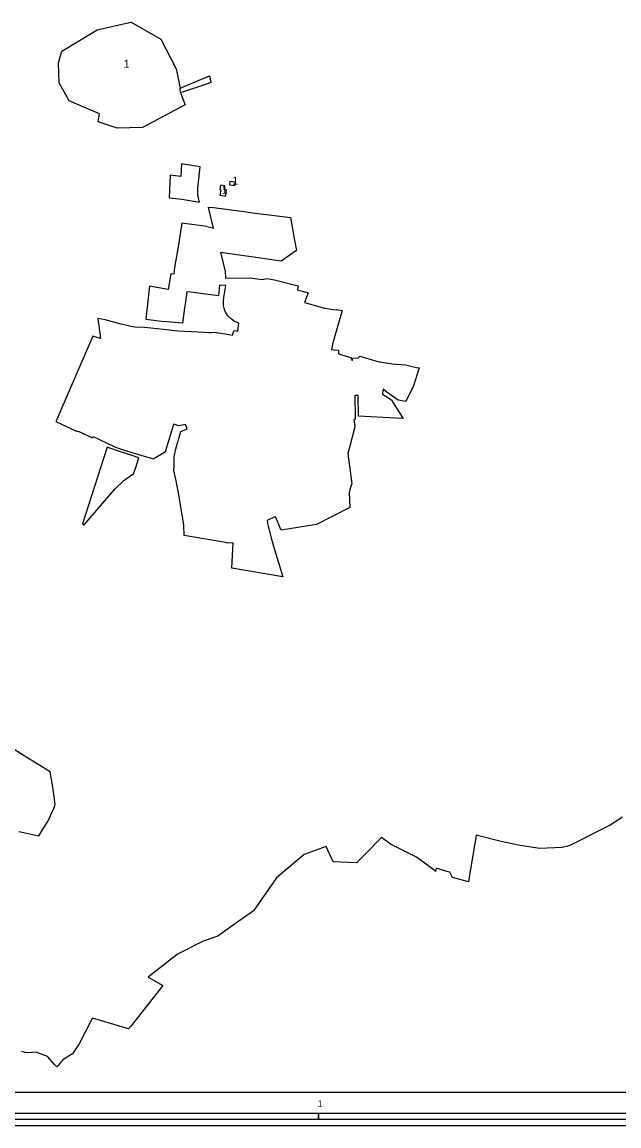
# Model space of a CAD drawing. Extents: x -790696 to -787271, y -1142331 to -1139378.
# Drawn here: x -789536 to -788602, y -1142329 to -1140605 of the extents above; entities that cross this region are included whole.
import ezdxf

# ---------------------------------------------------------------- set-up
doc = ezdxf.new("R2010")
doc.units = 0
for name, color, linetype in [('GR_MER', 7, 'Continuous'), ('NERES_HRA', 7, 'Continuous'), ('NERES_SET', 7, 'Continuous'), ('OVNE_PRE', 7, 'Continuous'), ('OVNE_SET', 7, 'Continuous'), ('OVNI_SET', 7, 'Continuous'), ('OZN', 7, 'Continuous')]:
    doc.layers.add(name, color=color, linetype=linetype)

msp = doc.modelspace()

# ---------------------------------------------------------------- linework, layer by layer
at = {"layer": 'GR_MER'}
for points in [[(-788475.3, -1142276.8), (-788475.3, -1142329.3), (-790086.7, -1142329.3), (-790086.7, -1142276.8), (-788475.3, -1142276.8)], [(-788572.2, -1142319.3), (-789072.2, -1142319.3), (-789072.2, -1142309.3), (-788572.2, -1142309.3)]]:
    msp.add_lwpolyline(points, dxfattribs=at)
msp.add_lwpolyline([(-789072.2, -1142319.3), (-789572.2, -1142319.3), (-789572.2, -1142309.3), (-789072.2, -1142309.3)], close=True, dxfattribs=at)
at = {"layer": 'NERES_HRA'}
msp.add_line((-789287.7, -1140715.3), (-789288.2, -1140708.2), dxfattribs=at)
at = {"layer": 'NERES_SET'}
for p, q in [((-789365.2, -1140604.8), (-789365.2, -1140604.8)), ((-789396.1, -1140751.4), (-789396.1, -1140751.4)), ((-789396.1, -1140751.4), (-789396.1, -1140751.4))]:
    msp.add_line(p, q, dxfattribs=at)
for points in [[(-789365.2, -1140604.8), (-789318.6, -1140631.6), (-789294.4, -1140677.6), (-789288.2, -1140708.2), (-789242.4, -1140688.7), (-789240.6, -1140699.2), (-789248.8, -1140702.2), (-789287.7, -1140715.3), (-789280.6, -1140733.8), (-789347.5, -1140769.6), (-789386.7, -1140770.7), (-789416.6, -1140760.4), (-789414.6, -1140748.3), (-789446.4, -1140734.5), (-789461.9, -1140727.7), (-789477.8, -1140699.9), (-789478.5, -1140668.2), (-789473.5, -1140650.4), (-789418.2, -1140617), (-789367.8, -1140605.3), (-789365.2, -1140604.8)], [(-789225.5, -1140859.3), (-789226.5, -1140866.4), (-789225, -1140866.6), (-789226.4, -1140875.3), (-789217.3, -1140876.7), (-789215.9, -1140867.6), (-789219.5, -1140867.1), (-789218.5, -1140860.4), (-789225.5, -1140859.3)], [(-789210.5, -1140853.9), (-789211.2, -1140858.8), (-789203.2, -1140860), (-789202.5, -1140855), (-789210.5, -1140853.9)]]:
    msp.add_lwpolyline(points, dxfattribs=at)
at = {"layer": 'OVNE_PRE'}
msp.add_lwpolyline([(-788596.7, -1141846.8), (-788616.1, -1141859.5), (-788679.2, -1141891.4), (-788682.3, -1141892.2), (-788691.5, -1141894.3), (-788726.1, -1141895.7), (-788757.1, -1141891), (-788779.4, -1141886.3), (-788786.7, -1141884.8), (-788825.8, -1141874.8), (-788837.3, -1141944.5), (-788837.9, -1141948), (-788843.4, -1141946.5), (-788862.6, -1141941.4), (-788866.8, -1141933.1), (-788869.6, -1141932.2), (-788888, -1141926.5), (-788889.1, -1141931.7), (-788891.4, -1141929.9), (-788919.1, -1141909.4), (-788959.6, -1141888.9), (-788973.9, -1141878.8), (-788999.4, -1141904.9), (-789006.3, -1141912.1), (-789012, -1141918.2), (-789049.2, -1141916.6), (-789060.1, -1141892.9), (-789094.4, -1141905.5), (-789137.7, -1141941.8), (-789173.8, -1141993.5), (-789205.5, -1142015.7), (-789229.6, -1142032.6), (-789249.1, -1142039.6), (-789253.6, -1142041.3), (-789292.4, -1142060.8), (-789338.2, -1142096.8), (-789315.7, -1142109.8)], dxfattribs=at)
at = {"layer": 'OVNE_SET'}
for points in [[(-789540.5, -1141869.1), (-789509.3, -1141875.9), (-789494.8, -1141852.6), (-789488.3, -1141838.5), (-789486, -1141833.3), (-789484.5, -1141828.7), (-789483.9, -1141826.5), (-789487.3, -1141799.8), (-789491.8, -1141776.2), (-789532.5, -1141750.9), (-789574.4, -1141724.8)], [(-789315.7, -1142109.8), (-789365, -1142172.7), (-789369, -1142177.7), (-789425.6, -1142161.1), (-789427.3, -1142164.6), (-789436.7, -1142182.8), (-789446.1, -1142200.9), (-789456.5, -1142216.7), (-789471.6, -1142226.1), (-789479.4, -1142235.3), (-789481.4, -1142236.9), (-789484.1, -1142233.9), (-789495.7, -1142220.8), (-789513.3, -1142214.1), (-789526.8, -1142215.2)], [(-789526.8, -1142215.2), (-789530.6, -1142214.6), (-789536, -1142212.8)]]:
    msp.add_lwpolyline(points, dxfattribs=at)
at = {"layer": 'OVNI_SET'}
msp.add_line((-789246.7, -1140924.3), (-789236.4, -1140926.6), dxfattribs=at)
for points in [[(-789257.1, -1140831), (-789286.3, -1140826.4), (-789287.1, -1140846.1), (-789304, -1140843.8), (-789305.5, -1140879.5), (-789285.1, -1140881.6), (-789282.9, -1140881.9), (-789258.1, -1140885.9), (-789258.6, -1140884.5), (-789260.7, -1140874.9), (-789260.6, -1140864.4), (-789259.3, -1140849.8), (-789257.1, -1140831)], [(-789244.3, -1140893.7), (-789236.4, -1140894.7), (-789200.8, -1140899.2), (-789188.2, -1140900.9), (-789178, -1140902.2), (-789175.3, -1140902.6), (-789145.1, -1140906.2), (-789115.9, -1140909.9), (-789110.1, -1140943), (-789106.6, -1140961.6), (-789130.6, -1140978.1), (-789188.5, -1140970.1), (-789225.2, -1140965), (-789224.4, -1140968.4), (-789218.2, -1140994.5)], [(-789236.4, -1140926.6), (-789243.1, -1140898.6), (-789244.3, -1140893.7)], [(-789246.7, -1140924.3), (-789285.6, -1140918.9), (-789291.2, -1140952.9), (-789297.5, -1140988), (-789298.2, -1140998.6), (-789303.1, -1140997.9), (-789307.4, -1141022.3), (-789336.5, -1141017.5), (-789342, -1141068.7), (-789313.5, -1141072.3)], [(-789218.2, -1140994.5), (-789217.4, -1141004.8), (-789179.1, -1141004.2), (-789160.9, -1141006.8), (-789152.4, -1141005.6), (-789141.1, -1141007.6), (-789103.7, -1141016.8), (-789105.2, -1141022), (-789105.5, -1141023), (-789097.7, -1141025.2), (-789088.4, -1141027.8), (-789094.1, -1141043.1), (-789063, -1141051.5), (-789061.4, -1141051.9), (-789049.6, -1141053.7), (-789044, -1141054.5), (-789043.7, -1141053.8), (-789035.3, -1141055.2), (-789049.7, -1141105.9), (-789051.7, -1141116.2), (-789047, -1141116.6), (-789040.8, -1141117.1), (-789040.8, -1141123.3), (-789028.7, -1141126.6), (-789021.4, -1141128.7), (-789019.7, -1141133.5), (-789018.4, -1141129.6), (-789010.1, -1141129.1), (-789007.6, -1141126.6), (-788979.2, -1141134.8), (-788957.2, -1141138.5), (-788936, -1141140.5), (-788927.6, -1141142.4), (-788918.7, -1141144.3), (-788914.9, -1141144.8), (-788923.6, -1141172.8), (-788935.5, -1141197.4), (-788947.8, -1141195.3), (-788966.9, -1141181.7), (-788971, -1141178.2), (-788972, -1141184.6), (-788972.3, -1141186), (-788958.2, -1141194.9), (-788955.4, -1141199.5), (-788945.5, -1141215.2), (-788939.6, -1141223.9), (-788971, -1141222.5), (-789009.5, -1141220.7)], [(-789232.3, -1141089.5), (-789218.2, -1141091.6), (-789206.7, -1141093.7), (-789205.3, -1141090.2), (-789203.8, -1141086.4), (-789198, -1141087.4), (-789197.5, -1141082.9), (-789196.9, -1141075), (-789203.6, -1141072.3), (-789208.9, -1141068.6), (-789213.5, -1141064), (-789217, -1141058.9), (-789219.1, -1141053.7), (-789220.5, -1141047.4), (-789220.8, -1141040.9), (-789220.2, -1141035.1), (-789217.1, -1141016.3), (-789226.9, -1141015.6), (-789228.3, -1141032.7), (-789272.3, -1141026.8), (-789277.9, -1141026.1), (-789280.2, -1141042), (-789281.4, -1141051), (-789284.7, -1141075.4), (-789303.7, -1141073.6), (-789313.5, -1141072.3)], [(-789405.4, -1141070.1), (-789417.3, -1141067.7), (-789413, -1141099.3), (-789425.1, -1141095.6), (-789459, -1141173.8), (-789481.2, -1141225.7), (-789482.6, -1141228.7), (-789449.4, -1141244.2), (-789449, -1141243.4), (-789425.6, -1141254.5), (-789424.4, -1141252), (-789391.8, -1141267.6), (-789385.1, -1141270.5), (-789375.9, -1141273.4), (-789350.1, -1141281.2), (-789341, -1141284), (-789337, -1141285.2), (-789330.8, -1141287.1), (-789326.9, -1141284.8), (-789311.2, -1141275.4), (-789298.3, -1141233.1)], [(-789243.8, -1141090.2), (-789260.5, -1141089.4), (-789292.1, -1141087.4), (-789314.6, -1141085), (-789344.2, -1141081.8), (-789359.5, -1141081.2), (-789367.6, -1141079.6), (-789380.7, -1141076.9), (-789405.4, -1141070.1)], [(-789232.3, -1141089.5), (-789239.3, -1141090.4), (-789243.8, -1141090.2)], [(-789009.5, -1141220.7), (-789010.2, -1141188.4), (-789011.5, -1141188.4), (-789015.6, -1141188.2), (-789015, -1141222.7), (-789014.8, -1141225.1), (-789017, -1141225.6), (-789015.1, -1141237), (-789023, -1141267.2), (-789026.4, -1141278.7), (-789020, -1141326.1), (-789020.5, -1141327.4), (-789021.9, -1141331.8), (-789023.2, -1141335.5), (-789024.1, -1141339.7), (-789023.4, -1141362.9), (-789075.5, -1141389.7), (-789130.4, -1141398.4), (-789139.2, -1141377.8), (-789141.5, -1141378), (-789152.6, -1141383.3), (-789151.7, -1141388.3), (-789150.9, -1141392.1), (-789145.7, -1141412.7), (-789142.3, -1141423.5), (-789128.1, -1141471.2), (-789207.4, -1141457.7), (-789205.4, -1141418.2), (-789214.9, -1141418.7), (-789214.8, -1141418.3), (-789235.7, -1141414.6), (-789282.2, -1141406.8), (-789282.8, -1141391.3), (-789283.6, -1141383.5), (-789285.7, -1141371.8), (-789289.8, -1141346.1), (-789294.9, -1141321.3), (-789298.1, -1141305.1)], [(-789298.1, -1141305.1), (-789298, -1141298.2), (-789297.6, -1141283.8), (-789295.3, -1141271.7), (-789287.4, -1141244.2), (-789283.6, -1141242.8), (-789277.3, -1141240.4), (-789279.9, -1141233.3), (-789290.6, -1141235.5), (-789298.3, -1141233.1)], [(-789352.8, -1141285.3), (-789365.2, -1141281.5), (-789365.7, -1141281.4), (-789386.4, -1141274.5), (-789402.7, -1141269.1), (-789441.2, -1141388.9), (-789438.5, -1141390.2), (-789390.4, -1141334.4), (-789376.3, -1141320.8), (-789364, -1141312.2), (-789361.3, -1141310.7), (-789356.8, -1141297.3), (-789356.7, -1141296.8), (-789352.8, -1141285.3)]]:
    msp.add_lwpolyline(points, dxfattribs=at)

# ---------------------------------------------------------------- texts
at = {"layer": 'GR_MER'}
msp.add_text('1', height=10, dxfattribs=at).set_placement((-789073.3, -1142299.3))
at = {"layer": 'OZN'}
for p in [(-789376.8, -1140676.1), (-789223.5, -1140872.9), (-789206.9, -1140858.8)]:
    msp.add_text('1', height=12.5, dxfattribs=at).set_placement(p)

doc.saveas('drawing.dxf')
